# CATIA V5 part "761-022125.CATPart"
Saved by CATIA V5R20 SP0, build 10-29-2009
Part number: 761-022125
Source: Unknown
Property "ARTICLENO": "761-022125"
Property "BOMINFO": "761-022125"
Property "CODE": "761-022125"
Property "H": "22.000"
Property "L1": "125.000"
Property "L2": "100.000"
Property "LINA": "761-022125"
Property "NB": "761-022125"
Property "NBSYN": "$CODE."
Property "NN": "761"
Property "NT": "VW/AUDI Keys"
Property "P": "4.000"
Property "SUPPLIER": "CF"
Bounding box of the stored display mesh (mm): x -62.5 to 62.5, y 0 to 22, z -11 to 11
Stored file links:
  C:\Users\Utente\Desktop\3D files 761\761-022125.CATPart
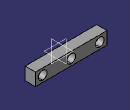
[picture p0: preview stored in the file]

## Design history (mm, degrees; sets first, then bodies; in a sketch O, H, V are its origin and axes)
Body1 "Geometry.1" (main body)
  Solid1 "761-022125.catpart": solid without history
